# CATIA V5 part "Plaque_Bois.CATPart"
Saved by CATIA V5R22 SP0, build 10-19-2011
Part number: Plaque_Bois
Bounding box of the stored display mesh (mm): x -570 to 570, y -570 to 570, z 0 to 15
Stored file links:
  D:\PER\CAO_PER_MODIF_2025\CAO_PER_pick&place_2024P\Plaque_Bois.CATPart
  D:\PER\CAO_PER_MODIF_2025\CAO_PER_pick&place_2024P\Assemblage.CATProduct
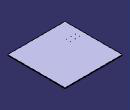
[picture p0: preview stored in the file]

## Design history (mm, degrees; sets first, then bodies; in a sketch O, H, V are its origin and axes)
Body1 (main body)
  Sketch1 on xy-plane, origin (0, 0, 0), H (1, 0, 0), V (0, 1, 0)
    line L1 (570, 570) -> (570, -570)
    line L2 (570, -570) -> (-570, -570)
    line L3 (-570, -570) -> (-570, 570)
    line L4 (-570, 570) -> (570, 570)
    length L1 = 1140
    length L4 = 1140
    vertical: L1 V, L3 V
    horizontal: L2 H, L4 H
    equidistance: L1 L3 O, L2 L4 O
  Pad1: profile Sketch1, direction (0, 0, 1), length 15
  DatumCurve1 to DatumCurve7
  Sketch2 on end face of Pad1, origin (0, 0, 15), H (1, 0, 0), V (0, 1, 0)
    circle A1 centre (-280.4263, -170) radius 3.5
    circle A2 centre (-370.4263, -170) radius 3.5
    circle A3 centre (-460.4263, -170) radius 3.5
    circle A4 centre (-280.4263, -248) radius 3.5
    circle A5 centre (-370.4263, -248) radius 3.5
    circle A6 centre (-460.4263, -248) radius 3.5
    reference projected circle E1 centre (-370.4263, -170) radius 3.5 from edge of DatumCurve1
    reference projected circle E2 centre (-370.4263, -170) radius 3.5 from edge of DatumCurve1
    reference projected circle E3 centre (-280.4263, -170) radius 3.5 from edge of DatumCurve2
    reference projected circle E4 centre (-280.4263, -170) radius 3.5 from edge of DatumCurve2
    reference projected circle E5 centre (-280.4263, -248) radius 3.5 from edge of DatumCurve3
    reference projected circle E6 centre (-370.4263, -248) radius 3.5 from edge of DatumCurve4
    reference projected circle E7 centre (-460.4263, -248) radius 3.5 from edge of DatumCurve5
    reference projected circle E8 centre (-460.4263, -170) radius 3.5 from edge of DatumCurve7
    reference projected circle E9 centre (-460.4263, -170) radius 3.5 from edge of DatumCurve7
    concentricity: A2 E1, A1 E3, A3 E8
    coincidence: A2 E2, A1 E4, A4 E5, A5 E6, A6 E7, A3 E9
  Pocket1: profile Sketch2, direction (0, 0, -1), length 20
